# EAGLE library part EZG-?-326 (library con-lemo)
LEMO Connector Source: http://www.lemo.com/pdfs/catalog/ROW/German/unipole_multipole.pdf
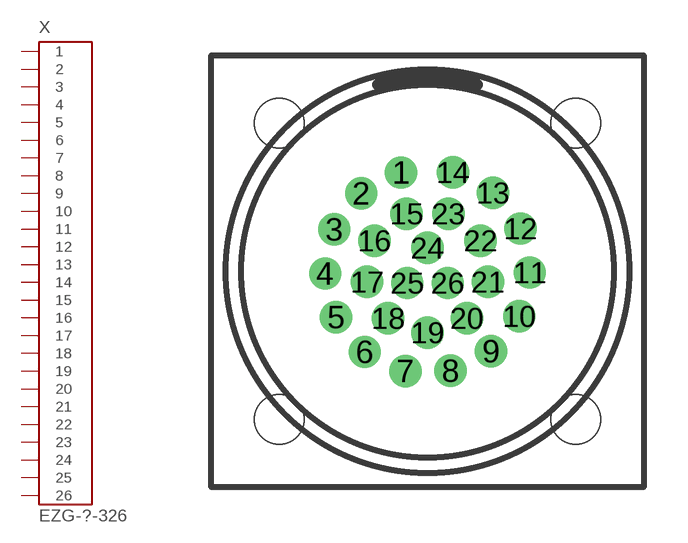
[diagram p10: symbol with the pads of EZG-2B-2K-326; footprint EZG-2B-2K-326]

Designator prefix X

## EZG-2B-326 (OC_FARNELL: unknown; OC_NEWARK: unknown)  [EZG-2B-2K-326]
1  1  pas
2  2  pas
3  3  pas
4  4  pas
5  5  pas
6  6  pas
7  7  pas
8  8  pas
9  9  pas
10  10  pas
11  11  pas
12  12  pas
13  13  pas
14  14  pas
15  15  pas
16  16  pas
17  17  pas
18  18  pas
19  19  pas
20  20  pas
21  21  pas
22  22  pas
23  23  pas
24  24  pas
25  25  pas
26  26  pas

## EZG-2K-326 (OC_FARNELL: unknown; OC_NEWARK: unknown)  [EZG-2B-2K-326]
Pads as for EZG-2B-2K-326

## Footprint EZG-2B-2K-326 (pad centres in mm)
LEMO Connector Source: http://www.lemo.com/pdfs/catalog/ROW/German/unipole_multipole.pdf
drill 0.6 pad 1 round: 1 -0.906,3.381; 2 -2.27,2.664; 3 -3.194,1.431; 4 -3.499,-0.079; 5 -3.126,-1.574; 6 -2.147,-2.764; 7 -0.753,-3.418; 8 0.788,-3.41; 9 2.176,-2.741; 10 3.142,-1.541; 11 3.5,-0.043; 12 3.179,1.464; 13 2.242,2.687; 14 0.871,3.39; 15 -0.718,1.973; 16 -1.819,1.05; 17 -2.068,-0.365; 18 -1.35,-1.609; 19 0,-2.1; 20 1.35,-1.609; 21 2.068,-0.365; 22 1.819,1.05; 23 0.718,1.973; 24 0,0.8; 25 -0.693,-0.4; 26 0.693,-0.4
hole 1.7 at -5.08,5.08
hole 1.7 at 5.08,5.08
hole 1.7 at 5.08,-5.08
hole 1.7 at -5.08,-5.08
